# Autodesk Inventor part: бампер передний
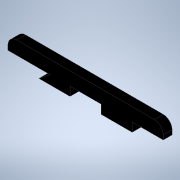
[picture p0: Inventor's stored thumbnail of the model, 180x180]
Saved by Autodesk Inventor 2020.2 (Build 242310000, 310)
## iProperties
Created: 2020-04
Part Number: бампер передний
Material: Типовые
Document SubType Name: Modeling
Designer: Алексей
Density: 1 g/cm^3
Appearance: По умолчанию
Author: Алексей
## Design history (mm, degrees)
sketch "Эскиз1"
  geometry: L1 (37, -4)-(23, -4) reference; L2 (37, 0)-(37, -4) reference; L3 (23, 0)-(37, 0) reference; L4 (23, 0)-(23, -4) reference; L5 (9, -4)-(-5, -4) reference; L6 (9, 0)-(9, -4) reference; L7 (0, 0)-(9, 0) reference; L8 (-15, 6)-(47, 6); L9 (51, 0)-(51, -3.372) reference; L10 (-19, -3.372)-(-19, 0) reference; L11 (-19, 0)-(-19, 2); L12 (51, 0)-(51, 2); L13 (51, 0)-(-19, 0); L14 (-5, 0)-(-5, -4) reference; A1 r 4 centre (-15, 2) between (-15, 6) and (-19, 2); A2 r 4 centre (47, 2) between (51, 2) and (47, 6); 5 further points
  constraints: 8 end point, 4 point on circle, 4 tangent, 2 centre point, 2 horizontal, 2 vertical, 1 equal radius
  dimensions: "d0" = 6 distance between parallel lines of L3 L8; "d1" = 4 radius of A1
extrude "Выдавливание1" new body sketch "Эскиз1" distance "d2" = 4; taper "d3" = 0 deg
node "Твердое тело1"
node "Ссылка1"
node "Ссылка3"
node "Ссылка4"
node "Ссылка5"
